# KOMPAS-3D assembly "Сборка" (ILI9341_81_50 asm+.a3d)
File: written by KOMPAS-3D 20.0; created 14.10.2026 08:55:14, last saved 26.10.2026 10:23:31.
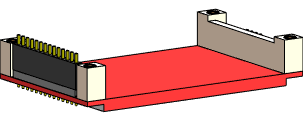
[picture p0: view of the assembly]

Document properties: Полное имя файла: D:\RicWork\Project-EPS32\box_compas\монитор\ILI9341_81_50 asm+.a3d

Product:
- Part/product: Сборка
    Масса: 0.129413
  - Component [detail]: Деталь  | Масса: 0.00428927; source file: ..\разъемы\pbs_14.m3d
  - Component [detail]: Деталь  | Масса: 0.000521406; source file: ..\разъемы\pls_4.m3d
  - Component [detail]: Деталь  | Масса: 0.00182492; source file: ..\разъемы\pls_14.m3d
  - Component [detail]: Деталь  | Масса: 0.0948715; source file: ILI9341_81х50.m3d
  - Component [assembly]: Сборка  | qty 2  | Масса: 0.0139528; source file: ..\корпус\п-стойка_1 asm.a3d

Referenced files in D:\RicWork\Project-EPS32\box_compas\монитор\: ILI9341_81х50.m3d
Referenced files in D:\RicWork\Project-EPS32\box_compas\разъемы\: pls_14.m3d, pls_4.m3d, pbs_14.m3d
Referenced files in D:\RicWork\Project-EPS32\box_compas\корпус\: п-стойка_1 asm.a3d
